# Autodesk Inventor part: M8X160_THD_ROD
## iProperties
Shininess: 64.0
Length Units: 11269
Angle Units: 11279
Time Units: 11290
Mass Units: 11283
Length Display Precision: 3
Angle Display Precision: 2
Compacted: True
Part Number: M8X160_THD_ROD
Document SubType Name: Modeling
Created: 2004-08
Material: Stainless Steel, Austenitic
Designer: John Blackburn
Manufacturer: Standard
Standards Organization: Custom
Density: 0.0
Volumn: 0.0
Area: 0.0
PropertySet Name: Model Information
Control State: 0
Master: False
Checked Out: False
Author: John Blackburn
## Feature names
1. Extrusion1
2. Chamfer1
